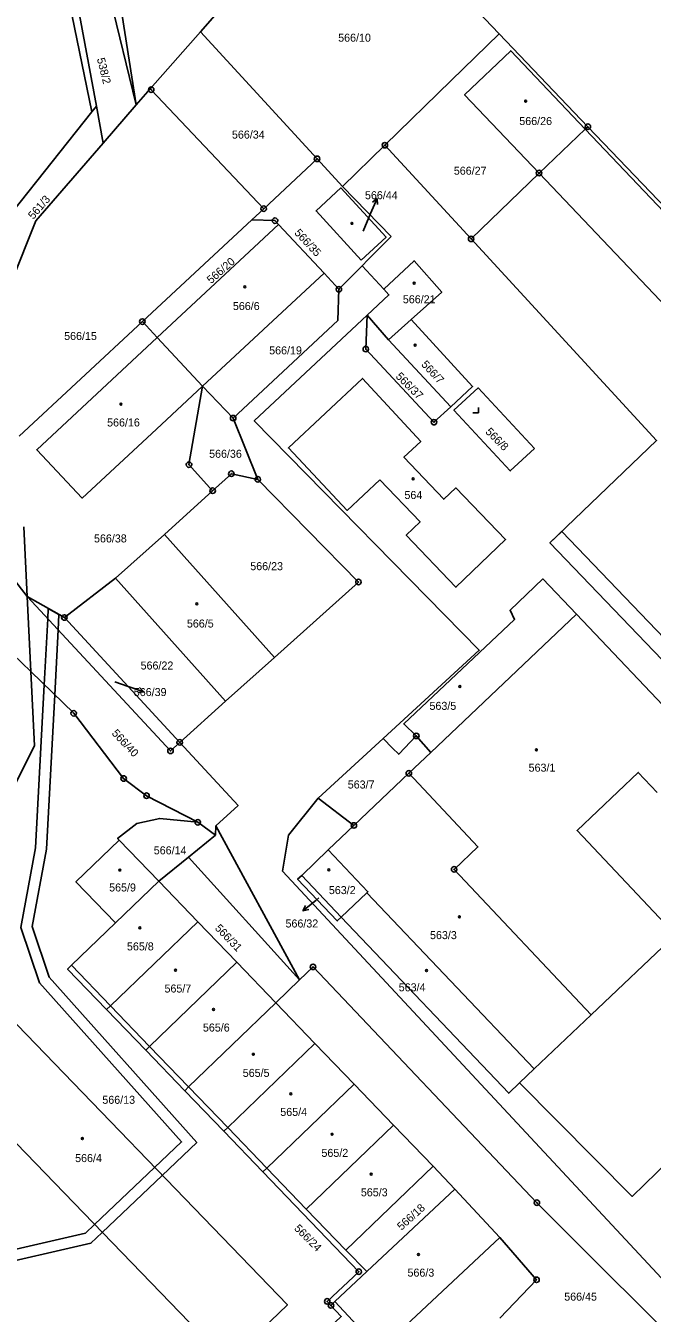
# Model space of a CAD drawing. Extents: x -587171 to -555306, y -1167727 to -1074732.
# Drawn here: x -560964.2 to -560849.9, y -1077893.1 to -1077658.3 of the extents above; entities that cross this region are included whole.
import ezdxf

# ---------------------------------------------------------------- set-up
doc = ezdxf.new("R2010")
doc.units = 0
for name, color, linetype in [('Hranice parcel', 7, 'Continuous'), ('Parcelní čísla', 7, 'Continuous'), ('Pop  PČ popisy', 7, 'Continuous'), ('Vnitřní kresba', 7, 'Continuous'), ('Věcná břemena k části', 7, 'Continuous'), ('Značky bodu BP', 7, 'Continuous'), ('Značky budov', 7, 'Continuous'), ('Značky kultur', 7, 'Continuous')]:
    doc.layers.add(name, color=color, linetype=linetype)

msp = doc.modelspace()

# ---------------------------------------------------------------- linework, layer by layer
at = {"layer": 'Hranice parcel'}
for p, q in [((-560932.31, -1077659.38), (-560906.37, -1077629.88)), ((-560894.18, -1077642.64), (-560877.81, -1077659.77)), ((-560954.88, -1077653.68), (-560951.31, -1077672.99)), ((-560944.05, -1077672.73), (-560948.87, -1077652.87)), ((-560941.47, -1077669.79), (-560932.31, -1077659.38)), ((-560932.31, -1077659.38), (-560911.04, -1077682.57)), ((-560877.81, -1077659.77), (-560861.63, -1077676.71)), ((-560944.05, -1077672.73), (-560941.47, -1077669.79)), ((-560952.12, -1077674.01), (-560951.31, -1077672.99)), ((-560951.31, -1077672.99), (-560950.07, -1077679.69)), ((-560950.07, -1077679.69), (-560944.05, -1077672.73)), ((-560862.1, -1077677.16), (-560870.54, -1077685.17)), ((-560861.63, -1077676.71), (-560862.1, -1077677.16)), ((-560861.63, -1077676.71), (-560748.88, -1077794.74)), ((-560898.66, -1077680.09), (-560906.4, -1077687.63)), ((-560882.94, -1077697.17), (-560898.66, -1077680.09)), ((-560920.78, -1077691.67), (-560911.04, -1077682.57)), ((-560911.04, -1077682.57), (-560906.4, -1077687.63)), ((-560870.54, -1077685.17), (-560882.94, -1077697.17)), ((-560906.4, -1077687.63), (-560897.55, -1077696.76)), ((-560922.95, -1077693.69), (-560920.78, -1077691.67)), ((-560942.92, -1077712.26), (-560922.95, -1077693.69)), ((-560918.05, -1077694.58), (-560940.2, -1077715.18)), ((-560909.77, -1077703.44), (-560918.05, -1077694.58)), ((-560897.55, -1077696.76), (-560907.06, -1077706.37)), ((-560931.94, -1077724.05), (-560909.77, -1077703.44)), ((-560907.06, -1077706.37), (-560909.77, -1077703.44)), ((-560902.15, -1077717.27), (-560901.91, -1077711.09)), ((-560901.91, -1077711.09), (-560898.02, -1077715.61)), ((-560965.39, -1077733.15), (-560942.92, -1077712.26)), ((-560942.92, -1077712.26), (-560940.2, -1077715.18)), ((-560893.86, -1077711.89), (-560898.02, -1077715.61)), ((-560940.2, -1077715.18), (-560931.94, -1077724.05)), ((-560898.02, -1077715.61), (-560886.66, -1077727.81)), ((-560931.94, -1077724.05), (-560926.35, -1077729.86)), ((-560926.35, -1077729.86), (-560921.86, -1077741.04)), ((-560930.1, -1077743.11), (-560938.88, -1077751.08)), ((-560964.57, -1077749.71), (-560963.95, -1077762.43)), ((-560938.88, -1077751.08), (-560947.82, -1077759.08)), ((-560918.82, -1077773.51), (-560938.88, -1077751.08)), ((-560963.95, -1077762.43), (-560969.51, -1077755.2)), ((-560947.82, -1077759.08), (-560957.15, -1077766.24)), ((-560947.82, -1077759.08), (-560927.74, -1077781.51)), ((-560963.28, -1077776.11), (-560963.95, -1077762.43)), ((-560963.95, -1077762.43), (-560957.15, -1077766.24)), ((-560957.15, -1077766.24), (-560936.1, -1077789.01)), ((-560863.73, -1077765.64), (-560890.31, -1077790.86)), ((-560863.73, -1077765.64), (-560840.5, -1077790.07)), ((-560963.28, -1077776.11), (-560968.18, -1077771.35)), ((-560918.82, -1077773.51), (-560927.74, -1077781.51)), ((-560927.74, -1077781.51), (-560936.1, -1077789.01)), ((-560892.94, -1077787.83), (-560890.31, -1077790.86)), ((-560890.31, -1077790.86), (-560894.3, -1077794.65)), ((-560894.3, -1077794.65), (-560904.32, -1077804.16)), ((-560932.81, -1077803.59), (-560942.15, -1077798.74)), ((-560929.58, -1077805.91), (-560932.81, -1077803.59)), ((-560908.99, -1077808.63), (-560904.32, -1077804.16)), ((-560939.92, -1077814.34), (-560947.14, -1077806.82)), ((-560929.58, -1077805.91), (-560934.49, -1077809.92)), ((-560939.92, -1077814.34), (-560934.49, -1077809.92)), ((-560934.49, -1077809.92), (-560914.25, -1077832.34)), ((-560913.85, -1077813.28), (-560908.99, -1077808.63)), ((-560939.92, -1077814.34), (-560947.8, -1077821.93)), ((-560932.81, -1077821.72), (-560939.92, -1077814.34)), ((-560913.85, -1077813.28), (-560906.63, -1077820.88)), ((-560906.63, -1077820.88), (-560901.96, -1077816.44)), ((-560901.96, -1077816.44), (-560871.42, -1077848.58)), ((-560925.69, -1077829.11), (-560932.81, -1077821.72)), ((-560955.83, -1077829.65), (-560947.8, -1077821.93)), ((-560918.57, -1077836.51), (-560925.69, -1077829.11)), ((-560914.25, -1077832.34), (-560911.78, -1077829.96)), ((-560918.57, -1077836.51), (-560914.25, -1077832.34)), ((-560942.31, -1077845.15), (-560949.44, -1077837.75)), ((-560911.45, -1077843.91), (-560918.57, -1077836.51)), ((-560861.04, -1077838.72), (-560871.42, -1077848.58)), ((-560935.19, -1077852.54), (-560942.31, -1077845.15)), ((-560904.29, -1077851.35), (-560911.45, -1077843.91)), ((-560871.42, -1077848.58), (-560874.09, -1077851.11)), ((-560904.29, -1077851.35), (-560920.2, -1077866.67)), ((-560897.09, -1077858.83), (-560904.29, -1077851.35)), ((-560928.06, -1077859.94), (-560935.19, -1077852.54)), ((-560913, -1077874.16), (-560897.09, -1077858.83)), ((-560889.87, -1077866.33), (-560897.09, -1077858.83)), ((-560920.92, -1077867.36), (-560928.06, -1077859.94)), ((-560905.79, -1077881.65), (-560889.87, -1077866.33)), ((-560885.89, -1077870.51), (-560889.87, -1077866.33)), ((-560920.92, -1077867.36), (-560920.2, -1077866.67)), ((-560920.2, -1077866.67), (-560913, -1077874.16)), ((-560885.89, -1077870.51), (-560901.93, -1077885.53)), ((-560877.71, -1077879.32), (-560885.89, -1077870.51)), ((-560913, -1077874.16), (-560905.79, -1077881.65)), ((-560870.99, -1077887.03), (-560877.71, -1077879.32)), ((-560905.79, -1077881.65), (-560901.93, -1077885.53)), ((-560901.93, -1077885.53), (-560907.78, -1077891.01)), ((-560877.69, -1077894), (-560870.99, -1077887.03)), ((-560907.78, -1077891.01), (-560908.51, -1077891.7))]:
    msp.add_line(p, q, dxfattribs=at)
for points in [[(-560952.12, -1077674.01), (-560966.12, -1077605.89), (-561018.09, -1077669.9)], [(-560916.1, -1077619.85), (-560938.99, -1077639.39), (-560947.41, -1077651.33), (-560944.05, -1077672.73)], [(-560898.66, -1077680.09), (-560886.57, -1077668.31), (-560877.81, -1077659.77)], [(-560870.54, -1077685.17), (-560884.13, -1077670.87), (-560875.7, -1077662.86), (-560862.1, -1077677.16)], [(-560920.78, -1077691.67), (-560941.3, -1077669.96), (-560941.47, -1077669.79)], [(-560971.12, -1077698.28), (-560966.6, -1077692.23), (-560952.12, -1077674.01)], [(-560870.54, -1077685.17), (-560829.87, -1077727.94), (-560821.43, -1077719.92), (-560862.1, -1077677.16)], [(-560950.07, -1077679.69), (-560962.35, -1077693.88), (-560966.77, -1077705.03)], [(-560903.01, -1077701.05), (-560911.23, -1077692.07), (-560906.68, -1077687.89), (-560898.44, -1077696.88), (-560903.01, -1077701.05)], [(-560918.05, -1077694.58), (-560918.72, -1077693.85), (-560922.95, -1077693.69)], [(-560783.34, -1077845.34), (-560791.1, -1077833.3), (-560868.56, -1077752.63), (-560849.09, -1077733.94), (-560882.94, -1077697.17)], [(-560901.91, -1077711.09), (-560897.94, -1077707.38), (-560898.88, -1077706.37), (-560893.33, -1077701.17), (-560888.29, -1077706.92), (-560893.86, -1077711.89)], [(-560907.06, -1077706.37), (-560907.26, -1077712.03), (-560926.35, -1077729.86)], [(-560893.86, -1077711.89), (-560882.65, -1077724.07), (-560886.66, -1077727.81)], [(-560940.2, -1077715.18), (-560962.18, -1077735.62), (-560953.89, -1077744.45), (-560940.33, -1077731.85), (-560931.94, -1077724.05)], [(-560886.66, -1077727.81), (-560889.71, -1077730.62), (-560902.15, -1077717.27)], [(-560899.57, -1077741.12), (-560892.25, -1077748.79), (-560894.78, -1077751.2), (-560885.72, -1077760.71), (-560876.64, -1077752.02), (-560885.75, -1077742.59), (-560887.92, -1077744.66), (-560895.18, -1077737), (-560892.11, -1077734.12), (-560902.78, -1077722.61), (-560916.28, -1077735.29), (-560905.52, -1077746.7), (-560899.57, -1077741.12)], [(-560931.94, -1077724.05), (-560934.42, -1077738.35), (-560930.1, -1077743.11)], [(-560871.37, -1077735.39), (-560875.8, -1077739.5), (-560886.07, -1077728.44), (-560881.66, -1077724.35), (-560871.37, -1077735.39)], [(-560921.86, -1077741.04), (-560926.68, -1077740.01), (-560930.1, -1077743.11)], [(-560921.86, -1077741.04), (-560903.49, -1077759.76), (-560918.82, -1077773.51)], [(-560892.94, -1077787.83), (-560895.23, -1077785.63), (-560874.99, -1077766.58), (-560875.83, -1077764.9), (-560869.87, -1077759.18), (-560863.73, -1077765.64)], [(-560963.95, -1077762.43), (-560937.78, -1077790.56), (-560936.1, -1077789.01)], [(-560963.28, -1077776.11), (-560962.62, -1077789.61), (-560966.7, -1077797.7), (-560976.39, -1077809.75), (-560995.18, -1077833.14)], [(-560942.15, -1077798.74), (-560946.34, -1077795.6), (-560955.45, -1077783.71), (-560963.28, -1077776.11)], [(-560904.32, -1077804.16), (-560910.85, -1077799.17), (-560899.01, -1077788.32), (-560897.25, -1077790.08), (-560896.13, -1077791.16), (-560892.94, -1077787.83)], [(-560936.1, -1077789.01), (-560925.46, -1077800.52), (-560929.52, -1077804.25), (-560929.58, -1077805.91)], [(-560894.3, -1077794.65), (-560881.68, -1077808.07), (-560886.04, -1077812.17), (-560861.04, -1077838.72)], [(-560861.04, -1077838.72), (-560845.65, -1077824.1), (-560863.61, -1077805.1), (-560852.45, -1077794.48), (-560848.96, -1077798.17)], [(-560947.14, -1077806.82), (-560947.43, -1077806.52), (-560943.95, -1077803.82), (-560939.76, -1077802.89), (-560932.81, -1077803.59)], [(-560947.8, -1077821.93), (-560955.03, -1077814.42), (-560947.14, -1077806.82)], [(-560901.96, -1077816.44), (-560901.75, -1077816.24), (-560908.99, -1077808.63)], [(-560906.63, -1077820.88), (-560907.35, -1077821.57), (-560914.59, -1077813.96), (-560913.85, -1077813.28)], [(-560932.81, -1077821.72), (-560948.71, -1077837.05), (-560949.44, -1077837.75)], [(-560874.09, -1077851.11), (-560876.08, -1077853), (-560906.63, -1077820.88)], [(-560990.26, -1077844.16), (-560986.69, -1077840.71), (-560983.52, -1077843.98), (-560927.31, -1077902.08), (-560916.46, -1077891.59), (-560972.62, -1077833.5), (-560979.27, -1077826.67), (-560990.15, -1077837.13), (-560992.43, -1077839.31)], [(-560949.44, -1077837.75), (-560956.56, -1077830.35), (-560955.83, -1077829.65)], [(-560925.69, -1077829.11), (-560941.59, -1077844.45), (-560942.31, -1077845.15)], [(-560911.78, -1077829.96), (-560870.93, -1077872.97), (-560839.79, -1077904.03)], [(-560815.28, -1077834.64), (-560853.53, -1077871.81), (-560874.09, -1077851.11)], [(-560918.57, -1077836.51), (-560934.47, -1077851.85), (-560935.19, -1077852.54)], [(-560911.45, -1077843.91), (-560927.34, -1077859.25), (-560928.06, -1077859.94)], [(-560908.51, -1077891.7), (-560909.19, -1077890.97), (-560903.43, -1077885.55), (-560920.92, -1077867.36)], [(-560907.78, -1077891.01), (-560899.57, -1077899.78), (-560877.71, -1077879.32)], [(-560932.64, -1077918.2), (-560906.64, -1077893.7), (-560908.51, -1077891.7)]]:
    msp.add_lwpolyline(points, dxfattribs=at)
at = {"layer": 'Pop  PČ popisy'}
for p, q in [((-560901.27, -1077692.54), (-560900.1, -1077689.78)), ((-560900.1, -1077689.78), (-560900.95, -1077690.5)), ((-560900.1, -1077689.78), (-560900.03, -1077690.9)), ((-560902.65, -1077695.79), (-560901.27, -1077692.54)), ((-560947.96, -1077777.95), (-560945.49, -1077778.79)), ((-560945.49, -1077778.79), (-560942.65, -1077779.77)), ((-560942.65, -1077779.77), (-560943.44, -1077778.97)), ((-560942.65, -1077779.77), (-560943.76, -1077779.91)), ((-560911.28, -1077817.86), (-560913.61, -1077819.75)), ((-560913.61, -1077819.75), (-560913.15, -1077818.73)), ((-560910.7, -1077817.39), (-560911.28, -1077817.86)), ((-560913.61, -1077819.75), (-560912.52, -1077819.51))]:
    msp.add_line(p, q, dxfattribs=at)
at = {"layer": 'Vnitřní kresba'}
for p, q in [((-560955.83, -1077829.65), (-560948.71, -1077837.05)), ((-560948.71, -1077837.05), (-560941.59, -1077844.45)), ((-560941.59, -1077844.45), (-560934.47, -1077851.85)), ((-560934.47, -1077851.85), (-560927.34, -1077859.25)), ((-560927.34, -1077859.25), (-560920.2, -1077866.67))]:
    msp.add_line(p, q, dxfattribs=at)
at = {"layer": 'Věcná břemena k části'}
msp.add_lwpolyline([(-560842.42, -1077892.93), (-560917.35, -1077812.48), (-560916.28, -1077805.96), (-560910.85, -1077799.17), (-560899.01, -1077788.32), (-560881.46, -1077772.21), (-560922.51, -1077730.37), (-560901.91, -1077711.09), (-560897.94, -1077707.38), (-560898.88, -1077706.37), (-560902.84, -1077702.1), (-560907.06, -1077706.37), (-560907.26, -1077712.03), (-560926.35, -1077729.86), (-560921.86, -1077741.04), (-560903.49, -1077759.76), (-560918.82, -1077773.51), (-560927.74, -1077781.51), (-560936.1, -1077789.01), (-560925.46, -1077800.52), (-560929.52, -1077804.25), (-560914.25, -1077832.34), (-560911.78, -1077829.96), (-560870.93, -1077872.97), (-560839.79, -1077904.03)], dxfattribs=at)
msp.add_lwpolyline([(-560842.42, -1077892.93), (-560917.35, -1077812.48), (-560916.28, -1077805.96), (-560910.85, -1077799.17), (-560899.01, -1077788.32), (-560881.46, -1077772.21), (-560922.51, -1077730.37), (-560901.91, -1077711.09), (-560897.94, -1077707.38), (-560898.88, -1077706.37), (-560902.84, -1077702.1), (-560907.06, -1077706.37), (-560907.26, -1077712.03), (-560926.35, -1077729.86), (-560921.86, -1077741.04), (-560903.49, -1077759.76), (-560918.82, -1077773.51), (-560927.74, -1077781.51), (-560936.1, -1077789.01), (-560925.46, -1077800.52), (-560929.52, -1077804.25), (-560914.25, -1077832.34), (-560911.78, -1077829.96), (-560870.93, -1077872.97), (-560839.79, -1077904.03)], dxfattribs=at)
for points in [[(-560866.4, -1077750.55), (-560868.56, -1077752.63), (-560791.1, -1077833.3), (-560783.34, -1077845.34), (-560778.08, -1077839.86), (-560788.94, -1077831.22), (-560801.74, -1077817.88), (-560804.52, -1077814.99)], [(-560960.09, -1077764.59), (-560960.19, -1077766.47), (-560960.83, -1077778.49), (-560962.4, -1077808.27), (-560965.07, -1077822.75), (-560961.7, -1077832.88), (-560935.77, -1077861.88), (-560940.68, -1077866.54), (-560951.63, -1077876.94), (-560953.3, -1077878.53), (-560972.35, -1077882.91), (-560971.9, -1077884.86), (-560952.32, -1077880.35), (-560950.24, -1077878.38), (-560939.29, -1077867.98), (-560932.99, -1077862), (-560959.94, -1077831.86), (-560963.01, -1077822.61), (-560960.4, -1077808.49), (-560958.91, -1077780.35), (-560958.29, -1077768.51), (-560958.14, -1077765.69)]]:
    msp.add_lwpolyline(points, close=True, dxfattribs=at)
at = {"layer": 'Značky bodu BP'}
for centre, radius in [((-560941.3, -1077669.96), 0.5), ((-560941.3, -1077669.96), 0.0303), ((-560861.63, -1077676.71), 0.5), ((-560861.63, -1077676.71), 0.0303), ((-560898.66, -1077680.09), 0.5), ((-560898.66, -1077680.09), 0.0303), ((-560911.04, -1077682.57), 0.5), ((-560911.04, -1077682.57), 0.0303), ((-560870.54, -1077685.17), 0.5), ((-560870.54, -1077685.17), 0.0303), ((-560920.78, -1077691.67), 0.5), ((-560920.78, -1077691.67), 0.0303), ((-560918.72, -1077693.85), 0.5), ((-560918.72, -1077693.85), 0.0303), ((-560882.94, -1077697.17), 0.5), ((-560882.94, -1077697.17), 0.0303), ((-560907.06, -1077706.37), 0.5), ((-560907.06, -1077706.37), 0.0303), ((-560942.92, -1077712.26), 0.5), ((-560942.92, -1077712.26), 0.0303), ((-560902.15, -1077717.27), 0.5), ((-560902.15, -1077717.27), 0.0303), ((-560926.35, -1077729.86), 0.5), ((-560926.35, -1077729.86), 0.0303), ((-560889.71, -1077730.62), 0.5), ((-560889.71, -1077730.62), 0.0303), ((-560934.42, -1077738.35), 0.5), ((-560934.42, -1077738.35), 0.0303), ((-560926.68, -1077740.01), 0.5), ((-560926.68, -1077740.01), 0.0303), ((-560921.86, -1077741.04), 0.5), ((-560921.86, -1077741.04), 0.0303), ((-560930.1, -1077743.11), 0.5), ((-560930.1, -1077743.11), 0.0303), ((-560903.49, -1077759.76), 0.5), ((-560903.49, -1077759.76), 0.0303), ((-560957.15, -1077766.24), 0.5), ((-560957.15, -1077766.24), 0.0303), ((-560955.45, -1077783.71), 0.5), ((-560955.45, -1077783.71), 0.0303), ((-560936.1, -1077789.01), 0.5), ((-560892.94, -1077787.83), 0.5), ((-560892.94, -1077787.83), 0.0303), ((-560937.78, -1077790.56), 0.5), ((-560937.78, -1077790.56), 0.0303), ((-560936.1, -1077789.01), 0.0303), ((-560946.34, -1077795.6), 0.5), ((-560946.34, -1077795.6), 0.0303), ((-560894.3, -1077794.65), 0.5), ((-560894.3, -1077794.65), 0.0303), ((-560942.15, -1077798.74), 0.5), ((-560942.15, -1077798.74), 0.0303), ((-560932.81, -1077803.59), 0.5), ((-560932.81, -1077803.59), 0.0303), ((-560904.32, -1077804.16), 0.5), ((-560904.32, -1077804.16), 0.0303), ((-560886.04, -1077812.17), 0.5), ((-560886.04, -1077812.17), 0.0303), ((-560911.78, -1077829.96), 0.5), ((-560911.78, -1077829.96), 0.0303), ((-560870.93, -1077872.97), 0.5), ((-560870.93, -1077872.97), 0.0303), ((-560903.43, -1077885.55), 0.5), ((-560903.43, -1077885.55), 0.0303), ((-560870.99, -1077887.03), 0.5), ((-560870.99, -1077887.03), 0.0303), ((-560909.19, -1077890.97), 0.5), ((-560909.19, -1077890.97), 0.0303), ((-560908.51, -1077891.7), 0.5), ((-560908.51, -1077891.7), 0.0303)]:
    msp.add_circle(centre, radius, dxfattribs=at)
at = {"layer": 'Značky budov'}
for centre in [(-560872.98, -1077672.04), (-560904.67, -1077694.34), (-560924.24, -1077705.9), (-560893.31, -1077705.25), (-560893.16, -1077716.54), (-560946.82, -1077727.3), (-560893.51, -1077740.94), (-560932.99, -1077763.76), (-560884.97, -1077778.82), (-560871.03, -1077790.35), (-560947.03, -1077812.29), (-560908.9, -1077812.26), (-560885.08, -1077820.83), (-560943.37, -1077822.84), (-560936.86, -1077830.56), (-560891.06, -1077830.63), (-560929.92, -1077837.71), (-560922.67, -1077845.9), (-560915.85, -1077853.1), (-560953.87, -1077861.27), (-560908.31, -1077860.49), (-560901.15, -1077867.74), (-560892.55, -1077882.41)]:
    msp.add_circle(centre, 0.175, dxfattribs=at)
at = {"layer": 'Značky kultur'}
for p, q in [((-560882.6, -1077728.91), (-560881.6, -1077728.91)), ((-560881.6, -1077728.91), (-560881.6, -1077727.91))]:
    msp.add_line(p, q, dxfattribs=at)

# ---------------------------------------------------------------- texts
at = {"layer": 'Parcelní čísla'}
for s, p in [('566/10', (-560907.19, -1077661.21)), ('566/26', (-560874.14, -1077676.41)), ('566/34', (-560926.57, -1077678.88)), ('566/27', (-560886.09, -1077685.47)), ('566/44', (-560902.3, -1077689.94)), ('566/6', (-560926.4, -1077710.15)), ('566/21', (-560895.39, -1077708.92)), ('566/15', (-560957.19, -1077715.62)), ('566/19', (-560919.78, -1077718.24)), ('566/16', (-560949.35, -1077731.39)), ('566/36', (-560930.74, -1077737.1)), ('564', (-560895.1, -1077744.62)), ('566/38', (-560951.74, -1077752.54)), ('566/23', (-560923.23, -1077757.6)), ('566/5', (-560934.79, -1077768.06)), ('566/22', (-560943.24, -1077775.72)), ('566/39', (-560944.48, -1077780.56)), ('563/5', (-560890.53, -1077783.08)), ('563/1', (-560872.44, -1077794.35)), ('563/7', (-560905.44, -1077797.42)), ('566/14', (-560940.84, -1077809.43)), ('565/9', (-560948.98, -1077816.2)), ('563/2', (-560908.89, -1077816.68)), ('566/32', (-560916.8, -1077822.77)), ('563/3', (-560890.43, -1077824.89)), ('565/8', (-560945.73, -1077826.95)), ('565/7', (-560938.88, -1077834.63)), ('563/4', (-560896.14, -1077834.41)), ('565/6', (-560931.87, -1077841.75)), ('565/5', (-560924.6, -1077850.02)), ('566/13', (-560950.22, -1077854.93)), ('565/4', (-560917.75, -1077857.14)), ('566/4', (-560955.19, -1077865.56)), ('565/2', (-560910.24, -1077864.61)), ('565/3', (-560903.05, -1077871.8)), ('566/3', (-560894.54, -1077886.45)), ('566/45', (-560865.94, -1077890.83))]:
    msp.add_text(s, height=1.46, dxfattribs=at).set_placement(p)
for s, rotation, p in [('538/2', 284, (-560951.22, -1077664.33)), ('561/3', 49, (-560962.82, -1077693.71)), ('566/35', 313, (-560915.28, -1077696.17)), ('566/20', 41, (-560930.38, -1077705.45)), ('566/7', 313, (-560892.13, -1077720.17)), ('566/37', 315, (-560896.8, -1077722.38)), ('566/8', 315, (-560880.43, -1077732.48)), ('566/40', 313, (-560948.6, -1077787.44)), ('566/31', 314, (-560929.78, -1077823.01)), ('566/18', 42, (-560895.64, -1077878.1)), ('566/24', 315, (-560915.32, -1077877.78))]:
    msp.add_text(s, height=1.46, rotation=rotation, dxfattribs=at).set_placement(p)

doc.saveas('drawing.dxf')
